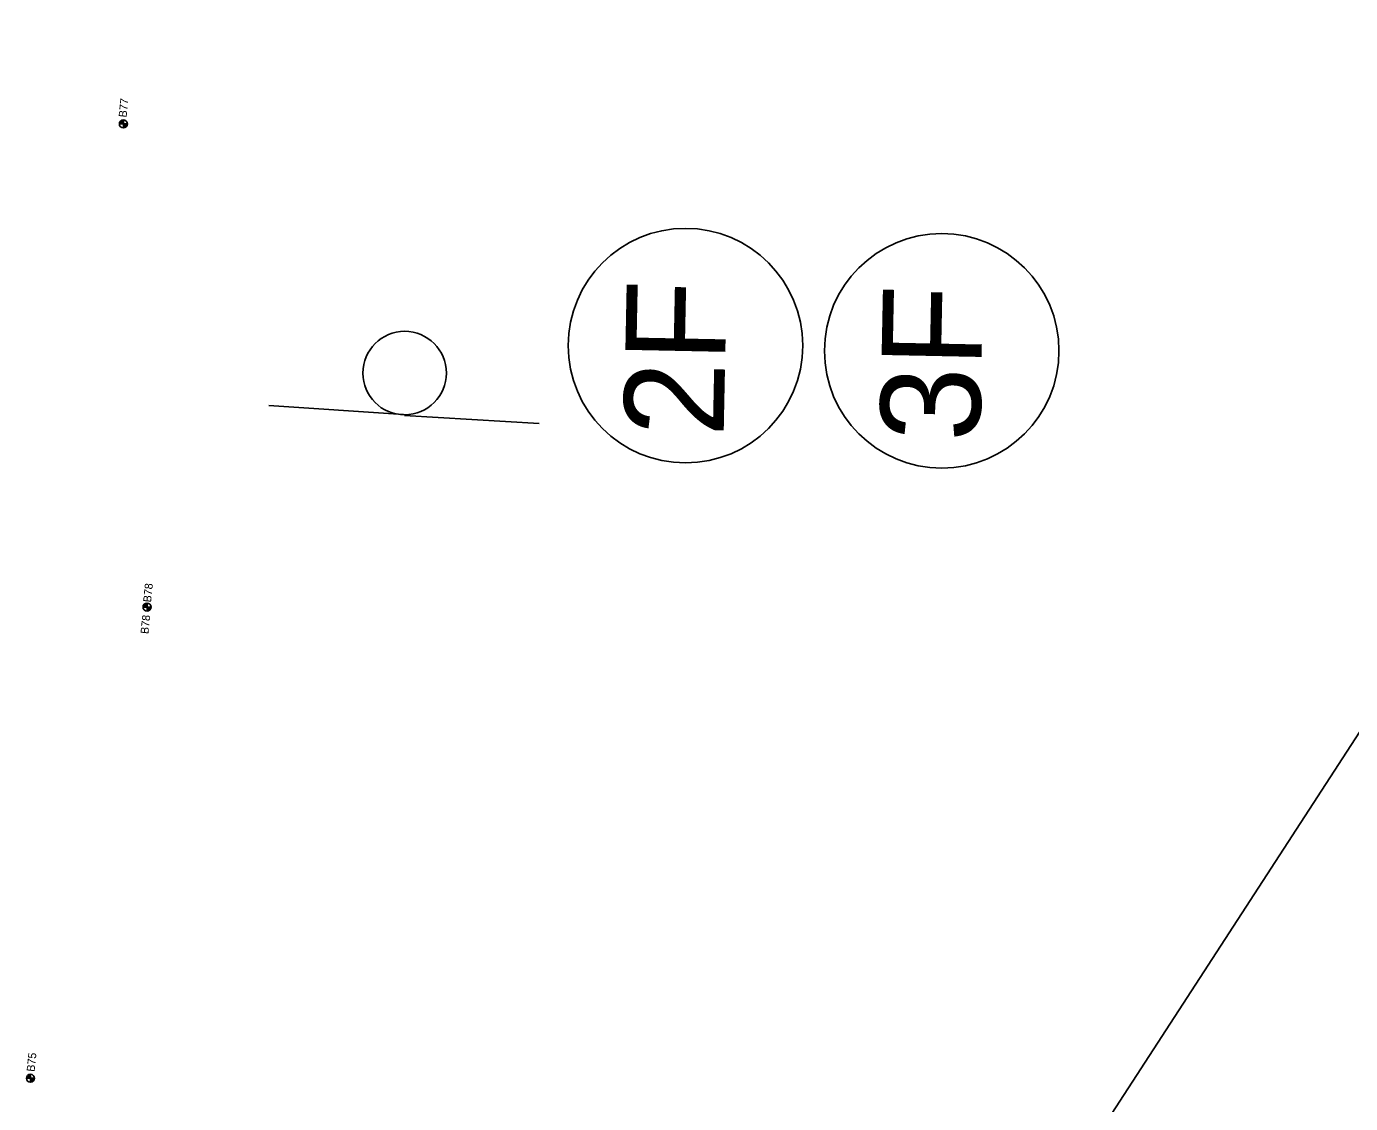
# Model space of a CAD drawing. Extents: x 327762 to 372792, y 127949 to 259367.
# Drawn here: x 359901 to 361556, y 172416 to 173763 of the extents above; entities that cross this region are included whole.
import ezdxf

# ---------------------------------------------------------------- set-up
doc = ezdxf.new("R2010")
doc.units = 0
for name, color, linetype in [('CA-TEXT', 7, 'Continuous'), ('E_SOIL_BORE1 [KAPUR_CADDS_LEVELS]', 7, 'Continuous'), ('E_SOIL_BORE2 [KAPUR_CADDS_LEVELS]', 7, 'Continuous'), ('P_MARK', 7, 'Continuous'), ('SIGNS-POLES', 7, 'Continuous')]:
    doc.layers.add(name, color=color, linetype=linetype)

msp = doc.modelspace()

# ---------------------------------------------------------------- linework, layer by layer
at = {"layer": 'CA-TEXT'}
msp.add_line((360416.7, 171107.8), (363211.3, 175412.4), dxfattribs=at)
for centre in [(360725.1, 173363.6), (361045.4, 173357.1)]:
    msp.add_circle(centre, 146.6, dxfattribs=at)
at = {"layer": 'P_MARK'}
for p, q in [((360017.5, 173640.8), (360027.5, 173640.8)), ((360022.5, 173645.8), (360022.5, 173635.8)), ((360052.1, 173041.8), (360052.1, 173031.8)), ((360047.1, 173036.8), (360057.1, 173036.8)), ((359901.4, 172447.6), (359911.4, 172447.6)), ((359906.4, 172452.6), (359906.4, 172442.6))]:
    msp.add_line(p, q, dxfattribs=at)
for centre in [(360022.5, 173640.8), (360052.1, 173036.8), (359906.4, 172447.6)]:
    msp.add_circle(centre, 5, dxfattribs=at)
for centre, radius, start, end in [((360022.5, 173640.8), 4.5, 89.9869, 179.9869), ((360022.5, 173640.8), 4, 89.9869, 179.9869), ((360022.5, 173640.8), 3.5, 89.9869, 179.9869), ((360022.5, 173640.8), 3, 89.9869, 179.9869), ((360022.5, 173640.8), 2.5, 89.9869, 179.9869), ((360022.5, 173640.8), 2, 89.9869, 179.9869), ((360022.5, 173640.8), 1.5, 89.9869, 179.9869), ((360022.5, 173640.8), 1, 89.9869, 179.9869), ((360022.5, 173640.8), 0.5, 89.9869, 179.9869), ((360022.5, 173640.8), 4.5, 269.9869, 359.9869), ((360022.5, 173640.8), 4, 269.9869, 359.9869), ((360022.5, 173640.8), 3.5, 269.9869, 359.9869), ((360022.5, 173640.8), 3, 269.9869, 359.9869), ((360022.5, 173640.8), 2.5, 269.9869, 359.9869), ((360022.5, 173640.8), 2, 269.9869, 359.9869), ((360022.5, 173640.8), 1.5, 269.9869, 359.9869), ((360022.5, 173640.8), 1, 269.9869, 359.9869), ((360022.5, 173640.8), 0.5, 269.9869, 359.9869), ((360052.1, 173036.8), 4.5, 89.9869, 179.9869), ((360052.1, 173036.8), 4, 89.9869, 179.9869), ((360052.1, 173036.8), 3.5, 89.9869, 179.9869), ((360052.1, 173036.8), 3, 89.9869, 179.9869), ((360052.1, 173036.8), 2.5, 89.9869, 179.9869), ((360052.1, 173036.8), 2, 89.9869, 179.9869), ((360052.1, 173036.8), 1.5, 89.9869, 179.9869), ((360052.1, 173036.8), 1, 89.9869, 179.9869), ((360052.1, 173036.8), 0.5, 89.9869, 179.9869), ((360052.1, 173036.8), 4.5, 269.9869, 359.9869), ((360052.1, 173036.8), 4, 269.9869, 359.9869), ((360052.1, 173036.8), 3.5, 269.9869, 359.9869), ((360052.1, 173036.8), 3, 269.9869, 359.9869), ((360052.1, 173036.8), 2.5, 269.9869, 359.9869), ((360052.1, 173036.8), 2, 269.9869, 359.9869), ((360052.1, 173036.8), 1.5, 269.9869, 359.9869), ((360052.1, 173036.8), 1, 269.9869, 359.9869), ((360052.1, 173036.8), 0.5, 269.9869, 359.9869), ((359906.4, 172447.6), 4.5, 89.9869, 179.9869), ((359906.4, 172447.6), 4, 89.9869, 179.9869), ((359906.4, 172447.6), 3.5, 89.9869, 179.9869), ((359906.4, 172447.6), 3, 89.9869, 179.9869), ((359906.4, 172447.6), 2.5, 89.9869, 179.9869), ((359906.4, 172447.6), 2, 89.9869, 179.9869), ((359906.4, 172447.6), 1.5, 89.9869, 179.9869), ((359906.4, 172447.6), 1, 89.9869, 179.9869), ((359906.4, 172447.6), 0.5, 89.9869, 179.9869), ((359906.4, 172447.6), 4.5, 269.9869, 359.9869), ((359906.4, 172447.6), 4, 269.9869, 359.9869), ((359906.4, 172447.6), 3.5, 269.9869, 359.9869), ((359906.4, 172447.6), 3, 269.9869, 359.9869), ((359906.4, 172447.6), 2.5, 269.9869, 359.9869), ((359906.4, 172447.6), 2, 269.9869, 359.9869), ((359906.4, 172447.6), 1.5, 269.9869, 359.9869), ((359906.4, 172447.6), 1, 269.9869, 359.9869), ((359906.4, 172447.6), 0.5, 269.9869, 359.9869)]:
    msp.add_arc(centre, radius, start, end, dxfattribs=at)
at = {"layer": 'SIGNS-POLES'}
for p, q in [((360372.6, 173277.4), (360204.3, 173288.7)), ((360542.3, 173266.1), (360373.8, 173276.1))]:
    msp.add_line(p, q, dxfattribs=at)
msp.add_circle((360374.1, 173329.3), 52.2, dxfattribs=at)

# ---------------------------------------------------------------- texts
at = {"layer": 'CA-TEXT'}
for s, p in [('2F', (360772.8, 173249.2)), ('3F', (361093.1, 173242.8))]:
    msp.add_text(s, height=124.99, rotation=88.8468, dxfattribs=at).set_placement(p)
at = {"layer": 'E_SOIL_BORE1 [KAPUR_CADDS_LEVELS]'}
for s, p in [('B77', (360026.5, 173648.6)), ('B78', (360057.1, 173042.3))]:
    msp.add_text(s, height=10, rotation=84.1728, dxfattribs=at).set_placement(p)
at = {"layer": 'E_SOIL_BORE2 [KAPUR_CADDS_LEVELS]'}
for s, p in [('B78', (360053.8, 173002.7)), ('B75', (359911.5, 172455.4))]:
    msp.add_text(s, height=10, rotation=84.1728, dxfattribs=at).set_placement(p)

doc.saveas('drawing.dxf')
